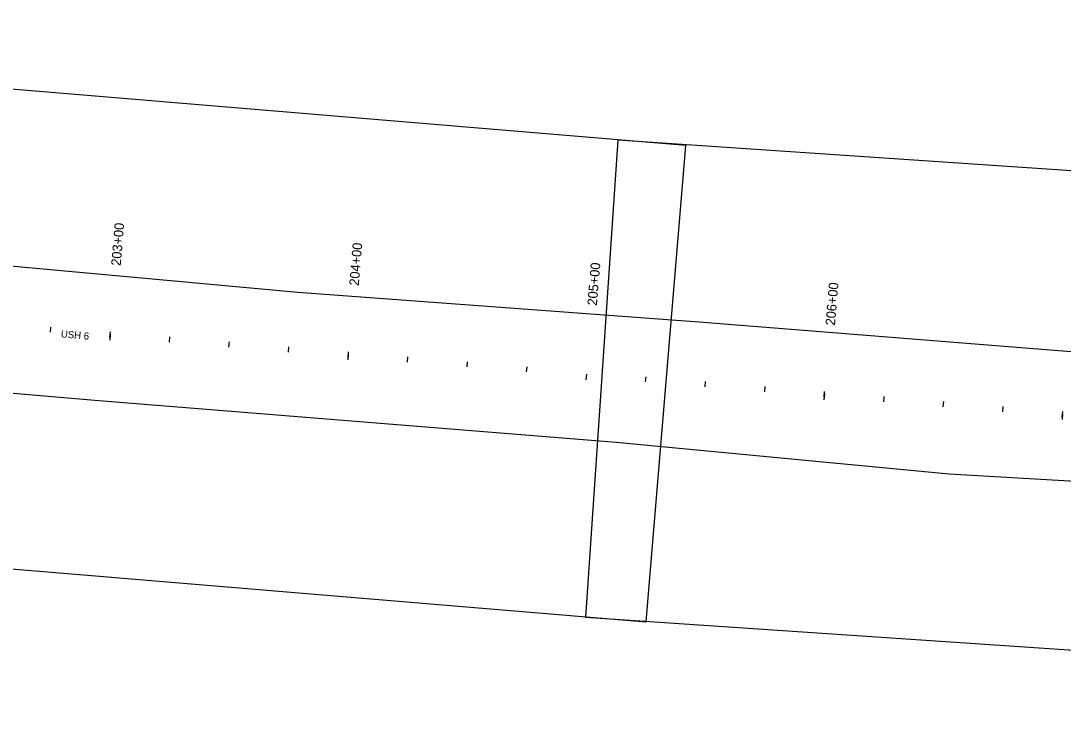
# Model space of a CAD drawing. Extents: x 20499876 to 20505320, y 7953544 to 7954108.
# Drawn here: x 20503963.1 to 20504399.3, y 7953543.8 to 7953835.6 of the extents above; entities that cross this region are included whole.
import ezdxf

# ---------------------------------------------------------------- set-up
doc = ezdxf.new("R2010")
doc.units = 0
for name, color, linetype in [('Draft_0', 7, 'Continuous'), ('Draft_7', 7, 'Continuous'), ('Drainage- Pipe', 7, 'Continuous'), ('PS_CONST', 7, 'Continuous'), ('Wall', 7, 'Continuous')]:
    doc.layers.add(name, color=color, linetype=linetype)

msp = doc.modelspace()

# ---------------------------------------------------------------- linework, layer by layer
at = {"layer": 'Draft_7'}
for p, q in [((20503975.46, 7953705.32), (20503975.64, 7953707.5)), ((20504000.48, 7953704.46), (20504000.27, 7953702.02)), ((20504025.29, 7953701.16), (20504025.47, 7953703.34)), ((20504050.2, 7953699.08), (20504050.38, 7953701.26)), ((20504075.11, 7953697), (20504075.3, 7953699.18)), ((20504100.13, 7953696.14), (20504099.93, 7953693.7)), ((20504124.94, 7953692.85), (20504125.12, 7953695.02)), ((20504149.85, 7953690.77), (20504150.04, 7953692.94)), ((20504174.77, 7953688.69), (20504174.95, 7953690.86)), ((20504199.78, 7953687.83), (20504199.58, 7953685.39)), ((20504224.59, 7953684.53), (20504224.78, 7953686.71)), ((20504249.51, 7953682.45), (20504249.69, 7953684.63)), ((20504274.42, 7953680.37), (20504274.6, 7953682.55)), ((20504299.44, 7953679.51), (20504299.23, 7953677.07)), ((20504324.25, 7953676.21), (20504324.43, 7953678.39)), ((20504349.16, 7953674.14), (20504349.34, 7953676.31)), ((20504374.08, 7953672.06), (20504374.26, 7953674.23)), ((20504399.09, 7953671.2), (20504398.89, 7953668.76))]:
    msp.add_line(p, q, dxfattribs=at)
at = {"layer": 'Drainage- Pipe'}
for points in [[(20503616.55, 7953835.62), (20503599.92, 7953636.31), (20504224.75, 7953584.17), (20504241.38, 7953783.48)], [(20504212.89, 7953785.63), (20504199.4, 7953586.08), (20504824.91, 7953543.82), (20504838.4, 7953743.37)]]:
    msp.add_lwpolyline(points, close=True, dxfattribs=at)
at = {"layer": 'PS_CONST'}
for p, q in [((20504000.37, 7953703.24), (20504000.56, 7953705.42)), ((20504100.03, 7953694.92), (20504100.21, 7953697.1)), ((20504199.78, 7953687.83), (20504199.58, 7953685.39)), ((20504299.33, 7953678.29), (20504299.52, 7953680.47)), ((20504398.99, 7953669.98), (20504399.17, 7953672.16))]:
    msp.add_line(p, q, dxfattribs=at)
at = {"layer": 'Wall'}
msp.add_lwpolyline([(20503829.09, 7953744.97), (20504079.02, 7953722.08), (20504247.03, 7953709.66), (20504477.95, 7953691.2), (20504693.1, 7953690.35), (20504707.3, 7953684.41), (20504703.39, 7953615.5), (20504682.83, 7953610.75), (20504591.14, 7953627.72), (20504566.72, 7953585.85), (20504541.05, 7953588.36), (20504519.52, 7953636.21), (20504351.61, 7953645.9), (20504212.21, 7953659.14), (20503994.1, 7953676.75), (20503832.88, 7953690.55)], dxfattribs=at)

# ---------------------------------------------------------------- texts
at = {"layer": 'Draft_0'}
msp.add_text('USH 6', height=3, rotation=355, dxfattribs=at).set_placement((20503979.75, 7953703.2))
at = {"layer": 'Draft_7'}
for s, rotation, p in [('203+00', 85.2296, (20504004.87, 7953732.97)), ('204+00', 85.2296, (20504104.52, 7953724.65)), ('205+00', 85.2296, (20504204.17, 7953716.34)), ('206+00', 85.2308, (20504303.83, 7953708.02))]:
    msp.add_text(s, height=4.008, rotation=rotation, dxfattribs=at).set_placement(p)
at = {"layer": 'PS_CONST'}
msp.add_text('205+00', height=4.008, rotation=85.2296, dxfattribs=at).set_placement((20504204.17, 7953716.34))

doc.saveas('drawing.dxf')
